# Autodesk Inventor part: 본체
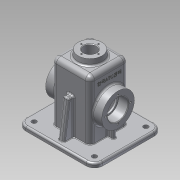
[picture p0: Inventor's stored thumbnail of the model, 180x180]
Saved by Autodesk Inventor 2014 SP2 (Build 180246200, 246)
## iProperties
Created: 2016-08
Part Number: 본체
Material: 알루미늄 6061
Document SubType Name: Modeling
Designer: user
Density: 2.71 g/cm^3
Appearance: 알루미늄 - 평지
Mass: 800.3 g
Surface Area: 911.822 cm^2
Volume: 295.314 cm^3
Author: user
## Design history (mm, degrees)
sketch "스케치1"
  geometry: L1 (-32.5, -32.5)-(32.5, -32.5); L2 (32.5, -32.5)-(32.5, 32.5); L3 (32.5, 32.5)-(-32.5, 32.5); L4 (-32.5, 32.5)-(-32.5, -32.5); L5 (-32.5, -32.5)-(32.5, 32.5); L6 (32.5, -32.5)-(-32.5, 32.5); 1 further point
  constraints: 12 end point, 2 midpoint, 2 parallel, 1 horizontal, 1 perpendicular
  dimensions: "d0" = 65 distance of L3.end L2.end; "d1" = 65 distance of L2.end L1.end
extrude "돌출1" new body sketch "스케치1" distance "d2" = 110; taper "d3" = 0 deg
feature "쉘1" dims "d4" = 5
sketch "스케치2"
  geometry: L1 (65, -57.5)-(-65, -57.5); L2 (-65, -57.5)-(-65, 57.5); L3 (-65, 57.5)-(65, 57.5); L4 (65, 57.5)-(65, -57.5); L5 (65, -57.5)-(-65, 57.5); L6 (-65, -57.5)-(65, 57.5); L7 (-27.5, 27.5)-(-27.5, -27.5) reference; L8 (-27.5, -27.5)-(27.5, -27.5) reference; L9 (27.5, -27.5)-(27.5, 27.5) reference; L10 (27.5, 27.5)-(-27.5, 27.5) reference; L11 (-32.5, -32.5)-(32.5, -32.5) reference; L12 (-32.5, 32.5)-(-32.5, -32.5) reference; L13 (32.5, 32.5)-(-32.5, 32.5) reference; L14 (32.5, -32.5)-(32.5, 32.5) reference; 1 further point
  constraints: 12 end point, 2 midpoint, 2 parallel, 1 horizontal, 1 perpendicular
  dimensions: "d5" = 130 distance of L2.end L3.end; "d6" = 115 distance of L3.end L1.start
extrude "돌출2" join sketch "스케치2" distance "d7" = 10; taper "d8" = 0 deg
fillet "모깎기1" dims "d9" = 14
fillet "모깎기2" dims "d10" = 8
fillet "모깎기3" dims "d11" = 8
fillet "모깎기4" dims "d12" = 3
fillet "모깎기5" dims "d13" = 3
sketch "스케치3"
  geometry: L1 (51, 57.5)-(-51, 57.5) reference; L2 (-65, 43.5)-(-65, -43.5) reference; L3 (-51, -57.5)-(51, -57.5) reference; L4 (65, -43.5)-(65, 43.5) reference; L5 (60, -52.5)-(-60, -52.5); L6 (-60, -52.5)-(-60, 52.5); L7 (-60, 52.5)-(60, 52.5); L8 (60, 52.5)-(60, -52.5); L9 (60, -52.5)-(-60, 52.5); L10 (-60, -52.5)-(60, 52.5); A1 r 14 centre (51, 43.5) between (65, 43.5) and (51, 57.5) reference; A2 r 14 centre (-51, 43.5) between (-51, 57.5) and (-65, 43.5) reference; A3 r 14 centre (-51, -43.5) between (-65, -43.5) and (-51, -57.5) reference; A4 r 14 centre (51, -43.5) between (51, -57.5) and (65, -43.5) reference; 1 further point
  constraints: 12 end point, 2 midpoint, 2 parallel, 1 horizontal, 1 perpendicular
  dimensions: "d14" = 120 distance of L6.end L7.end; "d15" = 105 distance of L5.end L6.end
extrude "돌출3" cut sketch "스케치3" distance "d16" = 3; taper "d17" = 0 deg
fillet "모깎기6" dims "d18" = 9
sketch "스케치4"
  geometry: L1 (51, 43.5)-(-51, 43.5); L2 (-51, 43.5)-(-51, -43.5); L3 (-51, -43.5)-(51, -43.5); L4 (51, -43.5)-(51, 43.5); L5 (51, 43.5)-(-51, -43.5); L6 (-51, 43.5)-(51, -43.5); A1 r 9 centre (-51, -43.5) between (-60, -43.5) and (-51, -52.5) reference; 5 further points
  constraints: 12 end point, 4 coincident, 2 midpoint, 2 parallel, 1 horizontal, 1 perpendicular
  dimensions: "d19" = 102 distance of L3.end L2.end (derived); "d20" = 87 distance of L2.end L1.end (derived)
hole "구멍1" sketch "스케치4" at (51, -43.5), (-51, -43.5), (-51, 43.5), (51, 43.5) diameter "d21" = 8; stored, may be unused: countersink angle "d25" = 90 deg, drill point angle "d27" = 118 deg; dims "d22" = 6, "d23" = 4, "d24" = 2, "d26" = 8
fillet "모깎기7" dims "d28" = 3
node "작업 평면1"
sketch "스케치5"
  geometry: L1 (-10, -19)-(-10, 68) reference; C1 r 27.5 at (45, 24.5); 2 further points
  constraints: 1 centre point, 1 horizontal alignment, 1 midpoint
  dimensions: "d30" = 55 diameter of C1; "d31" = 55 distance of point (-10, 24.5) C1.centre
extrude "돌출4" join sketch "스케치5" stored distance "d32" = 3; taper "d33" = 0 deg
fillet "모깎기8" dims "d34" = 3
hole "구멍2" diameter "d37" = 30; stored, may be unused: countersink angle "d41" = 90 deg, drill point angle "d43" = 118 deg; dims "d35" = 10, "d36" = 10, "d38" = 6, "d39" = 35, "d40" = 17, "d42" = 8
sketch "스케치6"
  geometry: L1 (27.5, 102)-(27.5, 0) reference; L2 (51, 10)-(-51, 10) reference; L3 (42.5, 10)-(42.5, 27.5); L4 (47.5, 27.5)-(35.5, 27.5) reference; 1 further point
  constraints: 2 end point, 2 point on line, 1 perpendicular
  dimensions: "d44" = 15 distance between parallel lines of L1 L3
feature "리브1" sketch "스케치6" dims "d45" = 1, "d46" = 6, "d47" = 0, "d48" = 0, "d49" = 1, "d50" = 1
sketch "스케치7" dims "d51" = 42
  geometry: C1 r 17.5 at (0, 0) reference; C2 r 27.5 at (0, 0) reference; 3 further points
  constraints: 2 vertical alignment, 1 coincident, 2 other
hole "구멍3" sketch "스케치7" at (0, 21) diameter "d52" = 3.242; stored, may be unused: countersink angle "d56" = 90 deg, drill point angle "d58" = 118 deg; dims "d53" = 8, "d54" = 35, "d55" = 17, "d57" = 10
chamfer "모따기1" distance "d62" = 1; stored, may be unused: second distance "d63" = 2, angle "d64" = 45 deg
fillet "모깎기9" dims "d65" = 0.3
chamfer "모따기2" distance "d66" = 1; stored, may be unused: second distance "d67" = 2, angle "d68" = 45 deg
fillet "모깎기10" dims "d69" = 0.3
fillet "모깎기11" dims "d70" = 3
node "작업 평면2"
sketch "스케치8"
  geometry: C1 r 20 at (0, 0); 1 further point
  constraints: 1 centre point, 1 coincident
  dimensions: "d72" = 40 diameter of C1
extrude "돌출5" join sketch "스케치8" stored distance "d73" = 3; taper "d74" = 7 deg
fillet "모깎기12" dims "d75" = 3
hole "구멍4" diameter "d78" = 21; stored, may be unused: countersink angle "d82" = 90 deg, drill point angle "d84" = 118 deg; dims "d76" = 10, "d77" = 10, "d79" = 8, "d80" = 35, "d81" = 17, "d83" = 10
chamfer "모따기3" distance "d85" = 1; stored, may be unused: second distance "d86" = 2, angle "d87" = 45 deg
sketch "스케치9" dims "d88" = 29
  geometry: C1 r 11.5 at (0, 0) reference; 2 further points
  constraints: 2 vertical alignment, 1 coincident, 2 other
hole "구멍5" sketch "스케치9" at (0, 14.5) diameter "d89" = 2.459; stored, may be unused: countersink angle "d93" = 90 deg, drill point angle "d95" = 118 deg; dims "d90" = 7, "d91" = 35, "d92" = 17, "d94" = 9
sketch "스케치10"
  geometry: L1 (-57.5, 3)-(-57.5, 7) reference; L2 (-54.5, 10)-(-43.5, 10) reference; L3 (-32.5, 10)-(-32.5, 102) reference; L4 (-49.5, 10)-(-41.068, 70); L5 (-41.068, 70)-(-32.5, 70); L6 (-43.5, 0)-(-52.5, 0) reference; 1 further point
  constraints: 4 end point, 2 point on line, 1 perpendicular
  dimensions: "d99" = 8 distance from line of L4.start L1; "d100" = 8 deg angle of L1 L4; "d101" = 70 distance between parallel lines of L6 L5
feature "리브2" sketch "스케치10" dims "d102" = 1, "d103" = 10, "d104" = 0, "d105" = 0, "d106" = 1, "d107" = 1
fillet "모깎기13" dims "d108" = 3
fillet "모깎기14" dims "d109" = 3
fillet "모깎기15" dims "d110" = 3
fillet "모깎기16" dims "d111" = 3
fillet "모깎기17" dims "d112" = 3
fillet "모깎기18" dims "d113" = 3
fillet "모깎기19" dims "d114" = 1
sketch "스케치11"
  geometry: L1 (-18, 4.5)-(-18, 44.5) reference; L2 (0, -8)-(91, -8) reference; 2 further points
  constraints: 1 other
  dimensions: "d115" = 32.5 distance from line of point (8, 24.5) L2; "d116" = 26 distance from line of point (8, 24.5) L1
feature "엠보싱1" sketch "스케치11" dims "d117" = 0.5, "d118" = 0
node "솔리드1"
pattern_circular "원형 패턴1" dims angle "d60" = 360 deg
mirror "대칭1"
pattern_circular "원형 패턴2" dims angle "d97" = 360 deg
mirror "대칭2"
node "투영된 루프1"
other parameters: "d29" = 15
